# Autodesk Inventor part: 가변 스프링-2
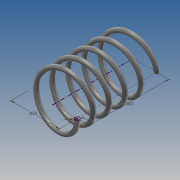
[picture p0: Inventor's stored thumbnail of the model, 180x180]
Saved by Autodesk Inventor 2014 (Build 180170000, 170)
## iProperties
Created: 2016-01
Part Number: 가변 스프링-2
Material: 스테인레스 스틸
Document SubType Name: Modeling
Designer: Administrator
Density: 8.08 g/cm^3
Appearance: 반연마
Mass: 8.67792 g
Surface Area: 21.7215 cm^2
Volume: 1.074 cm^3
Author: Administrator
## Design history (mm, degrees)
sketch "스케치1"
  geometry: L1 (0, 36.261)-(11, 36.261); L2 (11, 36.261)-(11, 0); L3 (11, 0)-(0, 0); L4 (0, 0)-(0, 36.261); C1 r 1 at (11, 0); 1 further point
  constraints: 8 end point, 2 coincident, 2 parallel, 1 centre point, 1 horizontal, 1 perpendicular
  dimensions: "d0" = 22 diameter of L2.end L4; "d1" = 36.2612 distance of L1.end L2.end (derived); "d2" = 2 diameter of C1
feature "코일1" pitch "d3" = 10; turns "d5" = 5; dims "d4" = 36.2612 (= d1), "d6" = 0, angle "d7" = 90 deg, angle "d8" = 90 deg, "d9" = 0, "d10" = 0
sketch "스케치2"
  geometry: L1 (-12, 0)-(-10, 0) reference; 1 further point
  constraints: 1 horizontal alignment
extrude "돌출1" cut sketch "스케치2" distance "d11" = 10; taper "d12" = 0 deg
node "작업 평면1"
sketch "스케치3"
  geometry: L1 (10, 0)-(12, 0) reference; 1 further point
  constraints: 1 horizontal alignment
extrude "돌출2" cut sketch "스케치3" distance "d14" = 10; taper "d15" = 0 deg
node "솔리드1"
node "절단 모서리 투영1"
node "절단 모서리 투영2"
other parameters: "d13" = 0
